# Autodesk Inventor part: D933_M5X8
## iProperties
Created: 2007-03
Part Number: D933_M5X8
Document SubType Name: Modeling
Designer: Andy Moles
Material: Steel
Density: 7.85 g/cm^3
Author: Andy Moles
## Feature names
1. Base1
